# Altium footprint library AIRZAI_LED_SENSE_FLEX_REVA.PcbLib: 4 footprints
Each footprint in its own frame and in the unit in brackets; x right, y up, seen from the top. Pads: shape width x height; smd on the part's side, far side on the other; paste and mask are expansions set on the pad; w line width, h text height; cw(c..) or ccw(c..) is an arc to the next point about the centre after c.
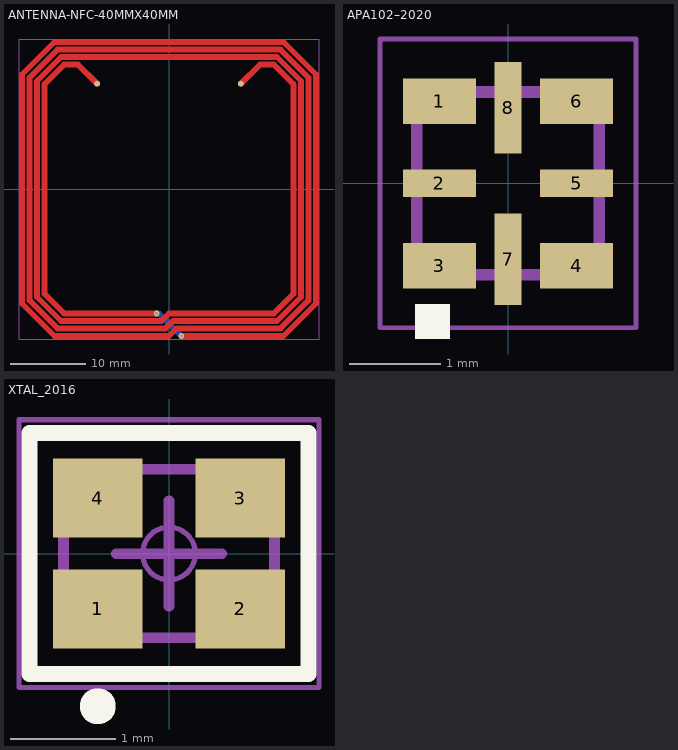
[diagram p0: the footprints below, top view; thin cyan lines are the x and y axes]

## ANTENNA-NFC-40MMX40MM [mil] "ANTENNA-ID2+10P-01"
pads (4):
  round 31.5 smd: 1(-377.5,552.5) 2(377.5,552.5)
  round 30 hole 15: 1(-65,-653.54) 2(65,-771.65)
Top Layer:
  lines w31.5: -377.5,552.5 -478.54,653.54 -550,653.54 -653.54,550 -653.54,-550 -550,-653.54 -65,-653.54 ; 65,-771.65 601.26,-771.65 771.65,-601.26 771.65,601.26 601.26,771.65 -601.26,771.65 -771.65,601.26 -771.65,-601.26 -601.26,-771.65 0,-771.65 39.37,-732.28 584.17,-732.28 732.28,-584.17 732.28,584.17 584.17,732.28 -584.17,732.28 -732.28,584.17 -732.28,-584.17 -584.17,-732.28 -19.37,-732.28 20,-692.91 567.09,-692.91 692.91,-567.09 692.91,567.09 567.09,692.91 -567.09,692.91 -692.91,567.09 -692.91,-567.09 -567.09,-692.91 -39.37,-692.91 0,-653.54 550,-653.54 653.54,-550 653.54,550 550,653.54 478.54,653.54 377.5,552.5
Bottom Layer:
  lines w31.5: -65,-653.54 -53.11,-653.54 65,-771.65
Mechanical 1:
  lines w3.94: -787.4,-787.4 -787.4,787.4 787.4,787.4 787.4,-787.4 -787.4,-787.4

## APA102–2020 [mm]
pads (8):
  rect 0.8x0.5 smd: 1(-0.75,0.9) 3(-0.75,-0.9) 4(0.75,-0.9) 6(0.75,0.9)
  rect 0.8x0.3 smd: 2(-0.75,0) 5(0.75,0)
  rect 0.3x1 smd: 7(0,-0.83) 8(0,0.83)
Top Overlay:
  rectangle: -1.016,-1.702 -0.635,-1.321
Mechanical 13 (Mech13):
  lines w0.127: -1,-1 1,-1 1,1 -1,1 -1,-1
Mechanical 16:
  lines w0.05: -1.4,-1.58 1.4,-1.58 1.4,1.58 -1.4,1.58 -1.4,-1.58
3D body: height 0.94, standoff 0, extent -0.698,0.254 -0.317,0.762
3D body: height 0.94, standoff 0, extent -0.19,0.254 0.191,0.762
3D body: height 0.94, standoff 0, extent 0.318,0.254 0.699,0.762
3D body: height 0.91, standoff 0, extent -1,-1 1,1

## PCBComponent_1 [mm]

## XTAL_2016 [mm] "2.00mm x 1.60mm"
height 1
pads (4):
  rect 0.85x0.75 smd: 1(-0.675,-0.525) 2(0.675,-0.525) 3(0.675,0.525) 4(-0.675,0.525)
Top Overlay:
  circle w0.3: c-0.675,-1.448 r0.02
  lines w0.152: -1.321,-1.143 -1.321,1.143 1.321,1.143 1.321,-1.143 -1.321,-1.143
Mechanical 1:
  text ".Designator" at -0.508,-0.229 h0.51
Mechanical 13 (Mech13):
  lines w0.1: -1,-0.8 1,-0.8 ; -1,0.8 1,0.8
  lines w0.102: -1,-0.8 -1,0.8 ; 1,-0.8 1,0.8
Mechanical 15:
  circle w0.05: c0,0 r0.25
  lines w0.05: -1.422,-1.27 1.422,-1.27 1.422,0.686 1.422,1.27 -1.422,1.27 -1.422,-1.27
  lines w0.1: -0.5,0 0.5,0 ; 0,-0.5 0,0.5
3D body "User Library-XRCGB27M000F2P00R0.STEP": height 0.65, standoff 0, extent -1,-0.813 1,0.787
